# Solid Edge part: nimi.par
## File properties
Author: Kasutaja
Template: Iso Metric Part.par
Last saved by: Kasutaja
Revision: 2
Application: Solid Edge
Username: Kasutaja
Accuracy: 0,990
Face Style: Model Default
Fill Style: Normal
Coef. of Thermal Exp: 0.0
Thermal Conductivity: 0.0
Specific Heat: 0.0
Modulus of Elasticity: 0.0
Poisson's Ratio: 0.0
Yield Stress: 0.0
Ultimate Stress: 0.0
Elongation: 0.0
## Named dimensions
RefPlane_5: Distance = 46.7154 mm
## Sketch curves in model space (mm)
spline (5.9334, 46.8832, 50.7474) -> (5.9274, 46.8849, 50.8122) -> (5.9512, 46.8782, 50.8831)
spline (5.963, 46.8748, 50.3558) -> (5.9549, 46.8771, 50.5024) -> (5.9334, 46.8832, 50.7474)
spline (5.9868, 46.868, 50.2386) -> (5.9805, 46.8698, 50.274) -> (5.963, 46.8748, 50.3558)
spline (5.9779, 46.8706, 50.1707) -> (5.984, 46.8688, 50.2162) -> (5.9868, 46.868, 50.2386)
spline (6.1677, 46.8165, 49.5046) -> (6.0603, 46.8471, 49.8349) -> (5.9779, 46.8706, 50.1707)
spline (6.2478, 46.7937, 49.3535) -> (6.2166, 46.8026, 49.4198) -> (6.1677, 46.8165, 49.5046)
spline (6.3694, 46.7591, 49.1191) -> (6.3846, 46.7547, 49.3366) -> (6.2478, 46.7937, 49.3535)
spline (6.8202, 46.6307, 48.7582) -> (6.5897, 46.6963, 48.8609) -> (6.3694, 46.7591, 49.1191)
spline (6.8885, 46.6112, 48.6225) -> (6.861, 46.619, 48.7008) -> (6.8202, 46.6307, 48.7582)
spline (7.4579, 46.449, 48.2679) -> (7.1129, 46.5473, 48.4137) -> (6.8885, 46.6112, 48.6225)
spline (7.4787, 46.4431, 48.3203) -> (7.4683, 46.4461, 48.2941) -> (7.4579, 46.449, 48.2679)
spline (7.5855, 46.4127, 48.3049) -> (7.5388, 46.426, 48.3138) -> (7.4787, 46.4431, 48.3203)
spline (7.6745, 46.3874, 48.2309) -> (7.6233, 46.402, 48.2794) -> (7.5855, 46.4127, 48.3049)
spline (8.3359, 46.199, 48.2124) -> (8.0141, 46.2907, 48.2093) -> (7.6745, 46.3874, 48.2309)
spline (8.3834, 46.1855, 48.2463) -> (8.3596, 46.1922, 48.2293) -> (8.3359, 46.199, 48.2124)
spline (8.6058, 46.1221, 48.2124) -> (8.5032, 46.1514, 48.2577) -> (8.3834, 46.1855, 48.2463)
spline (9.1219, 45.9751, 48.2833) -> (8.8516, 46.0521, 48.2409) -> (8.6058, 46.1221, 48.2124)
spline (9.2346, 45.943, 48.2895) -> (9.1783, 45.9591, 48.2864) -> (9.1219, 45.9751, 48.2833)
spline (9.4808, 45.8729, 48.3481) -> (9.3577, 45.908, 48.3188) -> (9.2346, 45.943, 48.2895)
spline (9.8011, 45.7817, 48.4097) -> (9.6475, 45.8255, 48.369) -> (9.4808, 45.8729, 48.3481)
spline (10.3113, 45.6364, 48.4745) -> (10.0721, 45.7045, 48.4353) -> (9.8011, 45.7817, 48.4097)
spline (10.6999, 45.5257, 48.5362) -> (10.5612, 45.5652, 48.5169) -> (10.3113, 45.6364, 48.4745)
spline (10.7384, 45.5148, 48.5732) -> (10.7191, 45.5203, 48.5547) -> (10.6999, 45.5257, 48.5362)
spline (11.1299, 45.4033, 48.6164) -> (10.8648, 45.4788, 48.5548) -> (10.7384, 45.5148, 48.5732)
spline (11.385, 45.3306, 48.6225) -> (11.3164, 45.3501, 48.6206) -> (11.1299, 45.4033, 48.6164)
spline (11.4473, 45.3129, 48.7058) -> (11.4117, 45.323, 48.6503) -> (11.385, 45.3306, 48.6225)
spline (11.5393, 45.2867, 48.7274) -> (11.4933, 45.2998, 48.7166) -> (11.4473, 45.3129, 48.7058)
spline (11.563, 45.2799, 48.8909) -> (11.5398, 45.2865, 48.8111) -> (11.5393, 45.2867, 48.7274)
spline (11.5274, 45.2901, 49.2116) -> (11.5218, 45.2917, 49.0411) -> (11.563, 45.2799, 48.8909)
spline (11.4948, 45.2994, 49.2887) -> (11.5178, 45.2928, 49.2397) -> (11.5274, 45.2901, 49.2116)
spline (11.4532, 45.3112, 49.2949) -> (11.4684, 45.3069, 49.2895) -> (11.4948, 45.2994, 49.2887)
spline (11.391, 45.3289, 49.3966) -> (11.4277, 45.3185, 49.3249) -> (11.4532, 45.3112, 49.2949)
spline (11.4532, 45.3112, 49.4244) -> (11.4221, 45.3201, 49.4105) -> (11.391, 45.3289, 49.3966)
spline (11.4888, 45.301, 49.5262) -> (11.4725, 45.3057, 49.4946) -> (11.4532, 45.3112, 49.4244)
spline (11.2338, 45.3737, 49.742) -> (11.3613, 45.3374, 49.6341) -> (11.4888, 45.301, 49.5262)
spline (11.3145, 45.3507, 49.7749) -> (11.2741, 45.3622, 49.7585) -> (11.2338, 45.3737, 49.742)
spline (11.3465, 45.3416, 50.0289) -> (11.3021, 45.3542, 49.8742) -> (11.3145, 45.3507, 49.7749)
spline (11.4177, 45.3213, 50.0289) -> (11.3821, 45.3315, 50.0289) -> (11.3465, 45.3416, 50.0289)
spline (11.4532, 45.3112, 50.8307) -> (11.4727, 45.3056, 50.53) -> (11.4177, 45.3213, 50.0289)
spline (11.474, 45.3053, 51.0558) -> (11.4512, 45.3118, 50.8647) -> (11.4532, 45.3112, 50.8307)
spline (11.4117, 45.323, 51.1946) -> (11.4597, 45.3093, 51.1059) -> (11.474, 45.3053, 51.0558)
spline (11.21, 45.3805, 51.1607) -> (11.3131, 45.3511, 51.1788) -> (11.4117, 45.323, 51.1946)
spline (11.2071, 45.3813, 51.1607) -> (11.2085, 45.3809, 51.1607) -> (11.21, 45.3805, 51.1607)
spline (11.0914, 45.4142, 51.1761) -> (11.1492, 45.3978, 51.1684) -> (11.2071, 45.3813, 51.1607)
spline (10.7859, 45.5012, 51.1885) -> (10.9593, 45.4519, 51.1638) -> (11.0914, 45.4142, 51.1761)
spline (10.6554, 45.5384, 51.1299) -> (10.7096, 45.523, 51.1346) -> (10.7859, 45.5012, 51.1885)
spline (10.2816, 45.6449, 51.1915) -> (10.4871, 45.5863, 51.1903) -> (10.6554, 45.5384, 51.1299)
spline (10.2075, 45.666, 50.9911) -> (10.0991, 45.6969, 51.0238) -> (10.2816, 45.6449, 51.1915)
spline (10.6939, 45.5274, 51.0034) -> (10.5436, 45.5703, 50.976) -> (10.2075, 45.666, 50.9911)
spline (10.7384, 45.5148, 50.9726) -> (10.7162, 45.5211, 50.988) -> (10.6939, 45.5274, 51.0034)
spline (10.9727, 45.448, 50.7289) -> (10.9027, 45.468, 50.9203) -> (10.7384, 45.5148, 50.9726)
spline (11.2516, 45.3686, 50.6642) -> (11.1332, 45.4023, 50.7177) -> (10.9727, 45.448, 50.7289)
spline (11.2397, 45.372, 50.6549) -> (11.249, 45.3694, 50.6572) -> (11.2516, 45.3686, 50.6642)
spline (11.0024, 45.4396, 50.072) -> (10.9965, 45.4413, 50.4565) -> (11.2397, 45.372, 50.6549)
spline (11.0083, 45.4379, 49.6588) -> (11.0345, 45.4304, 49.7669) -> (11.0024, 45.4396, 50.072)
spline (11.0024, 45.4396, 49.6372) -> (11.0048, 45.4389, 49.6434) -> (11.0083, 45.4379, 49.6588)
spline (11.2664, 45.3644, 49.3164) -> (11.1344, 45.402, 49.4768) -> (11.0024, 45.4396, 49.6372)
spline (11.0113, 45.437, 49.1684) -> (11.1388, 45.4007, 49.2424) -> (11.2664, 45.3644, 49.3164)
spline (11.2723, 45.3627, 49.0019) -> (11.1418, 45.3999, 49.0851) -> (11.0113, 45.437, 49.1684)
spline (10.9876, 45.4438, 48.8292) -> (11.0915, 45.4142, 48.9483) -> (11.2723, 45.3627, 49.0019)
spline (10.7503, 45.5114, 48.7582) -> (10.8967, 45.4697, 48.8053) -> (10.9876, 45.4438, 48.8292)
spline (10.2698, 45.6482, 48.7058) -> (10.4404, 45.5996, 48.7065) -> (10.7503, 45.5114, 48.7582)
spline (9.5906, 45.8417, 48.5701) -> (10.0463, 45.7119, 48.6353) -> (10.2698, 45.6482, 48.7058)
spline (9.5401, 45.856, 48.5115) -> (9.5665, 45.8485, 48.5466) -> (9.5906, 45.8417, 48.5701)
spline (8.68, 46.101, 48.4899) -> (9.1234, 45.9747, 48.5011) -> (9.5401, 45.856, 48.5115)
spline (8.6295, 46.1154, 48.5023) -> (8.6442, 46.1112, 48.499) -> (8.68, 46.101, 48.4899)
spline (8.5584, 46.1356, 48.4745) -> (8.6095, 46.1211, 48.4953) -> (8.6295, 46.1154, 48.5023)
spline (8.241, 46.226, 48.5454) -> (8.3926, 46.1829, 48.4711) -> (8.5584, 46.1356, 48.4745)
spline (7.5024, 46.4364, 48.7336) -> (8.0463, 46.2815, 48.3843) -> (8.241, 46.226, 48.5454)
spline (7.4817, 46.4423, 48.7089) -> (7.4921, 46.4393, 48.7212) -> (7.5024, 46.4364, 48.7336)
spline (7.455, 46.4499, 48.7521) -> (7.4683, 46.4461, 48.7305) -> (7.4817, 46.4423, 48.7089)
spline (7.3067, 46.4921, 48.8168) -> (7.3825, 46.4705, 48.7895) -> (7.455, 46.4499, 48.7521)
spline (6.752, 46.6501, 49.5231) -> (6.9849, 46.5838, 49.144) -> (7.3067, 46.4921, 48.8168)
spline (6.6897, 46.6678, 49.6218) -> (6.7275, 46.6571, 49.5574) -> (6.752, 46.6501, 49.5231)
spline (6.6156, 46.689, 49.8284) -> (6.6126, 46.6898, 49.5848) -> (6.6897, 46.6678, 49.6218)
spline (9.6291, 45.8307, 54.4143) -> (9.6558, 45.8231, 54.4205) -> (9.9198, 45.7479, 54.2756)
spline (9.5164, 45.8628, 54.3742) -> (9.5472, 45.854, 54.3827) -> (9.6291, 45.8307, 54.4143)
spline (9.2554, 45.9371, 54.3557) -> (9.3857, 45.9, 54.3673) -> (9.5164, 45.8628, 54.3742)
spline (9.1812, 45.9583, 54.3311) -> (9.2183, 45.9477, 54.3434) -> (9.2554, 45.9371, 54.3557)
spline (8.6028, 46.123, 54.2015) -> (8.8873, 46.042, 54.2616) -> (9.1812, 45.9583, 54.3311)
spline (8.3329, 46.1998, 54.1029) -> (8.4685, 46.1613, 54.1506) -> (8.6028, 46.123, 54.2015)
spline (8.0185, 46.2894, 53.9487) -> (8.169, 46.2465, 54.0249) -> (8.3329, 46.1998, 54.1029)
spline (8.0007, 46.2945, 53.8777) -> (8.0096, 46.2919, 53.8958) -> (8.0185, 46.2894, 53.9487)
spline (7.9266, 46.3156, 53.8222) -> (7.9792, 46.3006, 53.8523) -> (8.0007, 46.2945, 53.8777)
spline (7.8346, 46.3418, 53.8962) -> (7.8862, 46.3271, 53.8465) -> (7.9266, 46.3156, 53.8222)
spline (7.6329, 46.3992, 53.7297) -> (7.7538, 46.3648, 53.8338) -> (7.8346, 46.3418, 53.8962)
spline (7.3808, 46.471, 53.5631) -> (7.5069, 46.4351, 53.6464) -> (7.6329, 46.3992, 53.7297)
spline (7.3274, 46.4862, 53.5046) -> (7.3541, 46.4786, 53.5338) -> (7.3808, 46.471, 53.5631)
spline (7.2533, 46.5073, 53.449) -> (7.2904, 46.4968, 53.4768) -> (7.3274, 46.4862, 53.5046)
spline (7.1762, 46.5293, 53.3719) -> (7.2147, 46.5183, 53.4105) -> (7.2533, 46.5073, 53.449)
spline (6.7935, 46.6383, 53.0173) -> (7.0187, 46.5741, 53.2415) -> (7.1762, 46.5293, 53.3719)
spline (6.8143, 46.6324, 52.8723) -> (6.8039, 46.6353, 52.9448) -> (6.7935, 46.6383, 53.0173)
spline (6.6749, 46.6721, 52.8847) -> (6.7445, 46.6522, 52.8479) -> (6.8143, 46.6324, 52.8723)
spline (6.6096, 46.6906, 52.8199) -> (6.6323, 46.6842, 52.843) -> (6.6749, 46.6721, 52.8847)
spline (6.5296, 46.7134, 52.6842) -> (6.5696, 46.702, 52.752) -> (6.6096, 46.6906, 52.8199)
spline (6.408, 46.7481, 52.53) -> (6.4688, 46.7308, 52.6071) -> (6.5296, 46.7134, 52.6842)
spline (6.2715, 46.7869, 52.0181) -> (6.1792, 46.8132, 52.1108) -> (6.408, 46.7481, 52.53)
spline (6.2508, 46.7929, 51.907) -> (6.2611, 46.7899, 51.9625) -> (6.2715, 46.7869, 52.0181)
spline (6.1173, 46.8309, 51.907) -> (6.184, 46.8119, 51.907) -> (6.2508, 46.7929, 51.907)
spline (6.055, 46.8486, 51.7497) -> (6.0806, 46.8413, 51.8168) -> (6.1173, 46.8309, 51.907)
spline (5.963, 46.8748, 51.3642) -> (6.0321, 46.8551, 51.615) -> (6.055, 46.8486, 51.7497)
spline (5.9304, 46.8841, 51.099) -> (5.9445, 46.8801, 51.1981) -> (5.963, 46.8748, 51.3642)
spline (6.0105, 46.8613, 51.099) -> (5.9705, 46.8727, 51.099) -> (5.9304, 46.8841, 51.099)
spline (6.0461, 46.8511, 50.9109) -> (6.0283, 46.8562, 51.0188) -> (6.0105, 46.8613, 51.099)
spline (5.9512, 46.8782, 50.8831) -> (5.9986, 46.8647, 50.897) -> (6.0461, 46.8511, 50.9109)
spline (6.4613, 46.7329, 50.1646) -> (6.5073, 46.7198, 50.1538) -> (6.5533, 46.7067, 50.143)
spline (6.2092, 46.8047, 50.2016) -> (6.2719, 46.7868, 50.1842) -> (6.4613, 46.7329, 50.1646)
spline (6.5236, 46.7151, 50.2848) -> (6.3854, 46.7545, 50.2458) -> (6.2092, 46.8047, 50.2016)
spline (6.4732, 46.7295, 50.5192) -> (6.4963, 46.7229, 50.4058) -> (6.5236, 46.7151, 50.2848)
spline (6.4109, 46.7472, 50.51) -> (6.4421, 46.7384, 50.5146) -> (6.4732, 46.7295, 50.5192)
spline (6.4584, 46.7337, 50.7258) -> (6.373, 46.7581, 50.6298) -> (6.4109, 46.7472, 50.51)
spline (6.4613, 46.7329, 51.1083) -> (6.4411, 46.7386, 50.8919) -> (6.4584, 46.7337, 50.7258)
spline (6.3605, 46.7616, 51.2224) -> (6.4354, 46.7403, 51.1638) -> (6.4613, 46.7329, 51.1144)
spline (6.4673, 46.7312, 51.3026) -> (6.3939, 46.7521, 51.2706) -> (6.3605, 46.7616, 51.2224)
spline (6.5592, 46.705, 51.87) -> (6.5583, 46.7053, 51.6394) -> (6.4673, 46.7312, 51.3026)
spline (6.7253, 46.6577, 52.2401) -> (6.6067, 46.6915, 51.9286) -> (6.5592, 46.705, 51.87)
spline (6.7757, 46.6433, 52.3326) -> (6.7605, 46.6477, 52.3072) -> (6.7253, 46.6577, 52.2401)
spline (6.7817, 46.6416, 52.3943) -> (6.7776, 46.6428, 52.3519) -> (6.7757, 46.6433, 52.3326)
spline (6.7431, 46.6526, 52.3974) -> (6.7624, 46.6471, 52.3958) -> (6.7817, 46.6416, 52.3943)
spline (6.752, 46.6501, 52.4313) -> (6.7476, 46.6514, 52.4143) -> (6.7431, 46.6526, 52.3974)
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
